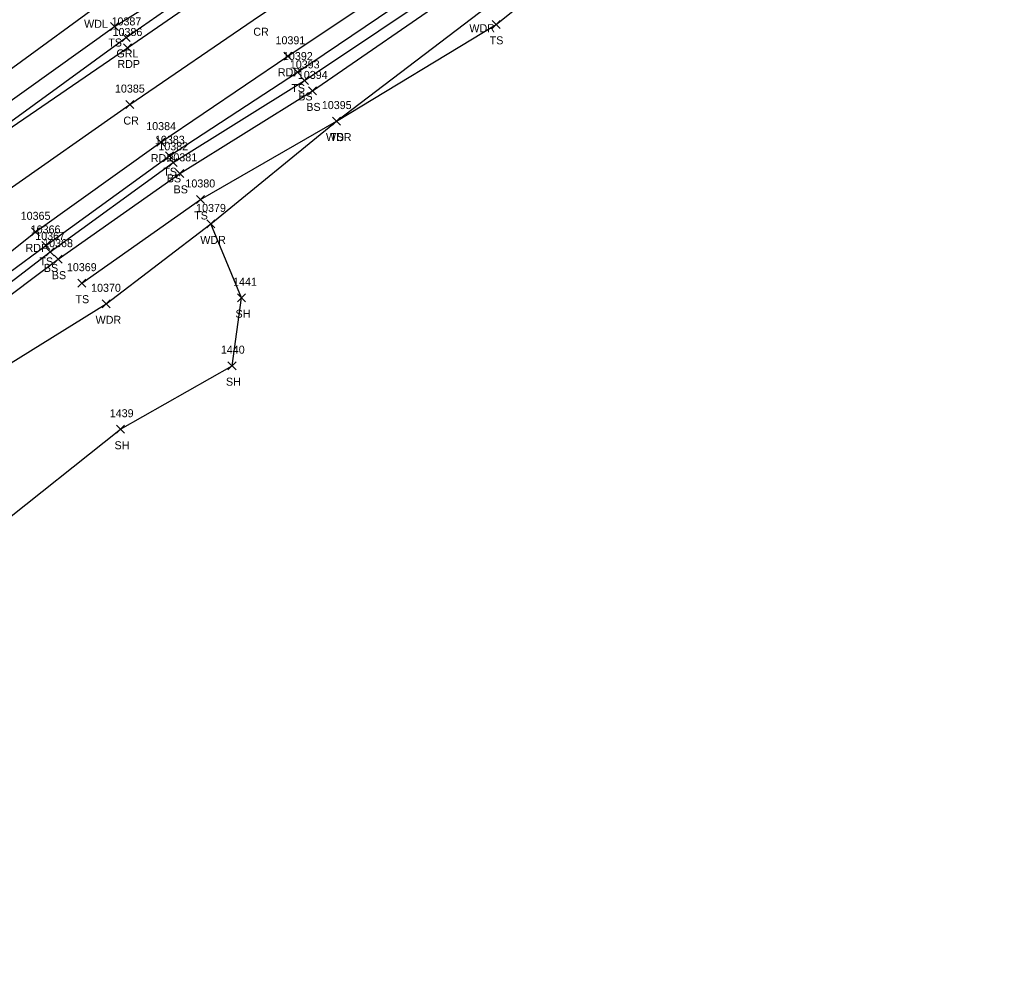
# Model space of a CAD drawing. Extents: x 1651685 to 1653558, y 889533 to 891085.
# Drawn here: x 1652940.5 to 1653187.7, y 890489.8 to 890725 of the extents above; entities that cross this region are included whole.
import ezdxf

# ---------------------------------------------------------------- set-up
doc = ezdxf.new("R2010")
doc.units = 0
for name, color, linetype in [('L_A', 7, 'Continuous'), ('L_I', 7, 'Continuous'), ('L_TIC', 7, 'Continuous'), ('LAWA', 7, 'Continuous'), ('LELB', 7, 'Continuous'), ('LSOGP', 7, 'Continuous'), ('P_A', 7, 'Continuous'), ('P_I', 7, 'Continuous'), ('P_TIC', 7, 'Continuous'), ('PET', 7, 'Continuous'), ('PRC', 7, 'Continuous'), ('R_A', 7, 'Continuous'), ('R_I', 7, 'Continuous'), ('R_TIC', 7, 'Continuous'), ('RGR', 7, 'Continuous')]:
    doc.layers.add(name, color=color, linetype=linetype)

msp = doc.modelspace()

# ---------------------------------------------------------------- linework, layer by layer
at = {"layer": 'L_TIC'}
for points in [[(1652963.24, 890722.35), (1652965.24, 890724.35)], [(1652965.24, 890722.35), (1652963.24, 890724.35)], [(1653058.51, 890722.89), (1653060.51, 890724.89)], [(1653060.51, 890722.89), (1653058.51, 890724.89)], [(1653008.95, 890710.96), (1653010.95, 890712.96)], [(1653010.95, 890710.96), (1653008.95, 890712.96)], [(1653010.67, 890708.88), (1653012.67, 890710.88)], [(1653012.67, 890708.88), (1653010.67, 890710.88)], [(1653012.67, 890706.26), (1653014.67, 890708.26)], [(1653014.67, 890706.26), (1653012.67, 890708.26)], [(1653018.66, 890698.72), (1653020.66, 890700.72)], [(1653020.66, 890698.72), (1653018.66, 890700.72)], [(1653018.66, 890698.72), (1653020.66, 890700.72)], [(1653020.66, 890698.72), (1653018.66, 890700.72)], [(1652976.97, 890690.06), (1652978.97, 890692.06)], [(1652978.97, 890690.06), (1652976.97, 890692.06)], [(1652977.83, 890688.41), (1652979.83, 890690.41)], [(1652979.83, 890688.41), (1652977.83, 890690.41)], [(1652979.52, 890685.66), (1652981.52, 890687.66)], [(1652981.52, 890685.66), (1652979.52, 890687.66)], [(1652984.68, 890679.14), (1652986.68, 890681.14)], [(1652986.68, 890679.14), (1652984.68, 890681.14)], [(1652987.27, 890673.02), (1652989.27, 890675.02)], [(1652989.27, 890673.02), (1652987.27, 890675.02)], [(1652946.04, 890667.65), (1652948.04, 890669.65)], [(1652948.04, 890667.65), (1652946.04, 890669.65)], [(1652947.11, 890666.03), (1652949.11, 890668.03)], [(1652949.11, 890666.03), (1652947.11, 890668.03)], [(1652949.1, 890664.22), (1652951.1, 890666.22)], [(1652951.1, 890664.22), (1652949.1, 890666.22)], [(1652955.04, 890658.22), (1652957.04, 890660.22)], [(1652957.04, 890658.22), (1652955.04, 890660.22)], [(1652994.94, 890654.58), (1652996.94, 890656.58)], [(1652996.94, 890654.58), (1652994.94, 890656.58)], [(1652961.12, 890653.07), (1652963.12, 890655.07)], [(1652963.12, 890653.07), (1652961.12, 890655.07)], [(1652992.55, 890637.61), (1652994.55, 890639.61)], [(1652994.55, 890637.61), (1652992.55, 890639.61)], [(1652964.72, 890621.73), (1652966.72, 890623.73)], [(1652966.72, 890621.73), (1652964.72, 890623.73)]]:
    msp.add_lwpolyline(points, dxfattribs=at)
at = {"layer": 'LAWA'}
for points in [[(1652817.98, 890613.54), (1652840.14, 890627.46), (1652861.15, 890647.29), (1652878.51, 890666.18), (1652884.26, 890671.52), (1652922.69, 890701.4), (1652959.19, 890728.02), (1652986.15, 890746.08), (1653025.9, 890769.89), (1653049.43, 890788.17), (1653075.47, 890803.38), (1653097.52, 890818.66), (1653132.33, 890844.48)], [(1652833.35, 890477.68), (1652833.39, 890492.3), (1652850.18, 890532.6), (1652867.73, 890564.2), (1652876.6, 890576.01), (1652892.95, 890598.85), (1652902.11, 890607.6), (1652908.8, 890618.44), (1652924.22, 890630.58), (1652962.12, 890654.07), (1652988.27, 890674.02), (1653019.66, 890699.72), (1653055.48, 890726.92), (1653095, 890752.3), (1653138.9, 890781.66), (1653162.63, 890798.14), (1653173.84, 890802.86)]]:
    msp.add_lwpolyline(points, dxfattribs=at)
at = {"layer": 'LELB'}
for points in [[(1652773.03, 890464.56), (1652787.9, 890509.35), (1652802.92, 890548.75), (1652814.17, 890571.87), (1652832.16, 890602.17), (1652848.73, 890624.66), (1652866.01, 890644.23), (1652889.12, 890668.57), (1652926.33, 890696.32), (1652964.24, 890723.35), (1652991.22, 890740.2), (1653028.13, 890766.86), (1653057.75, 890784.91), (1653079.01, 890799.53), (1653102.53, 890813.78), (1653139.28, 890840.79)], [(1652801.17, 890441.9), (1652819.95, 890497.78), (1652834.5, 890541.46), (1652846.59, 890562.12), (1652860.39, 890582.03), (1652876.07, 890602.68), (1652893.78, 890623.65), (1652912.56, 890642.08), (1652928.52, 890655.01), (1652947.04, 890668.65), (1652977.97, 890691.06), (1653009.95, 890711.96), (1653047.06, 890737.13), (1653086.67, 890762.46), (1653129.22, 890790.4), (1653161.56, 890810.77), (1653178.09, 890819.36), (1653180.64, 890814.31), (1653173.84, 890802.86)], [(1652803.19, 890441), (1652820.95, 890497.33), (1652835.58, 890541.15), (1652847.79, 890560.97), (1652861.63, 890580.86), (1652877.83, 890601.57), (1652890.21, 890617.22), (1652895.56, 890622.27), (1652897.12, 890622.95), (1652897.22, 890624.03), (1652915.57, 890639.3), (1652930.05, 890653.23), (1652948.11, 890667.03), (1652978.83, 890689.41), (1653011.67, 890709.88), (1653048.76, 890734.73), (1653087.02, 890761.14), (1653131.31, 890788.11), (1653159.98, 890805.73), (1653164.16, 890807.03), (1653164.17, 890807.66), (1653169.82, 890813.7), (1653178.09, 890819.36)], [(1652803.19, 890441), (1652822.35, 890480.19), (1652822.96, 890495.87), (1652838.19, 890539.83), (1652849.62, 890560.27), (1652863.19, 890579.04), (1652878.87, 890600.11), (1652891.82, 890615.8), (1652896.5, 890621.01), (1652897.47, 890622.7), (1652898.8, 890623.23), (1652915.57, 890639.3), (1652950.1, 890665.22), (1652980.52, 890686.66), (1653013.67, 890707.26), (1653050.87, 890733.01), (1653089.27, 890757.95), (1653133.42, 890785.98), (1653160.95, 890802.08), (1653164.63, 890804.85), (1653167.22, 890806.35), (1653170.81, 890811.17), (1653178.09, 890819.36)], [(1652956.04, 890659.22), (1652985.68, 890680.14), (1653019.66, 890699.72), (1653059.51, 890723.89)]]:
    msp.add_lwpolyline(points, dxfattribs=at)
at = {"layer": 'LSOGP'}
msp.add_lwpolyline([(1652860.84, 890470.43), (1652866.91, 890496.63), (1652876.03, 890531.03), (1652888.38, 890556.27), (1652912.99, 890585.04), (1652934.21, 890597.75), (1652965.72, 890622.73), (1652993.55, 890638.61), (1652995.94, 890655.58), (1652988.27, 890674.02), (1653019.66, 890699.72), (1653059.51, 890723.89), (1653095, 890752.3), (1653138.9, 890781.66), (1653162.63, 890798.14), (1653173.85, 890802.86), (1653182.19, 890805.28), (1653198.8, 890815.08)], dxfattribs=at)
at = {"layer": 'P_TIC'}
for points in [[(1652966.44, 890716.98), (1652968.44, 890718.98)], [(1652968.44, 890716.98), (1652966.44, 890718.98)], [(1653006.52, 890714.91), (1653008.52, 890716.91)], [(1653008.52, 890714.91), (1653006.52, 890716.91)], [(1652966.99, 890702.84), (1652968.99, 890704.84)], [(1652968.99, 890702.84), (1652966.99, 890704.84)], [(1652974.79, 890693.46), (1652976.79, 890695.46)], [(1652976.79, 890693.46), (1652974.79, 890695.46)], [(1652943.49, 890671.05), (1652945.49, 890673.05)], [(1652945.49, 890671.05), (1652943.49, 890673.05)]]:
    msp.add_lwpolyline(points, dxfattribs=at)
at = {"layer": 'PET'}
for points in [[(1652776.68, 890458.63), (1652791.9, 890507.53), (1652801.72, 890533.82), (1652810.09, 890553.36), (1652823.07, 890577.38), (1652836.65, 890598.71), (1652853.5, 890620.62), (1652874.5, 890644.55), (1652894.69, 890663.43), (1652909.83, 890677.02), (1652929.28, 890691.96), (1652967.44, 890717.98), (1652993.7, 890736.14), (1653032.31, 890761.89), (1653070.4, 890786.93), (1653112.15, 890813.99), (1653148.48, 890837.47), (1653192.87, 890865.71), (1653235.94, 890893.09), (1653280.18, 890921.16), (1653320.29, 890946.68)], [(1652797.7, 890444.76), (1652815.98, 890499.36), (1652826.44, 890526.94), (1652833.17, 890541.97), (1652844.38, 890563.93), (1652857.27, 890583.87), (1652872.84, 890604.95), (1652891.59, 890626.08), (1652910.84, 890643.86), (1652926.01, 890657.3), (1652944.49, 890672.05), (1652975.79, 890694.46), (1653007.52, 890715.91), (1653044.82, 890740.95), (1653083.79, 890766.34), (1653126.92, 890794.39), (1653162.42, 890817.19), (1653177.23, 890826.53), (1653212.82, 890849.27), (1653251.6, 890873.99), (1653294.22, 890900.69), (1653334.65, 890925.85)]]:
    msp.add_lwpolyline(points, dxfattribs=at)
at = {"layer": 'PRC'}
msp.add_lwpolyline([(1652786.21, 890448.94), (1652804.54, 890503.78), (1652815.08, 890532.72), (1652822.08, 890547.99), (1652834.04, 890571.05), (1652846.73, 890591.11), (1652862.72, 890612.73), (1652882.99, 890635.62), (1652902.76, 890654.37), (1652917.73, 890667.19), (1652936.47, 890681.71), (1652967.99, 890703.84), (1653000.43, 890726.04), (1653038.85, 890751.54), (1653077.14, 890776.73), (1653119.4, 890804.03), (1653156.21, 890827.39), (1653198.86, 890855.33), (1653243.54, 890883.44), (1653287.35, 890911.24), (1653327.74, 890936.2)], dxfattribs=at)
at = {"layer": 'R_TIC'}
for points in [[(1652966.13, 890719.62), (1652968.13, 890721.62)], [(1652968.13, 890719.62), (1652966.13, 890721.62)]]:
    msp.add_lwpolyline(points, dxfattribs=at)
at = {"layer": 'RGR'}
msp.add_lwpolyline([(1652753.62, 890407.5), (1652763.75, 890431.04), (1652774.48, 890459.79), (1652790.93, 890508.17), (1652800.51, 890534.29), (1652809.1, 890554.07), (1652821.88, 890578.18), (1652835.53, 890599.08), (1652852.44, 890621.25), (1652873.86, 890645.38), (1652894.3, 890664.88), (1652909.53, 890677.55), (1652928.71, 890692.69), (1652967.13, 890720.62), (1652991.99, 890738.03), (1653030.5, 890764.27), (1653069.01, 890789.08), (1653110.73, 890816.31), (1653147.12, 890839.54), (1653191.34, 890868.1), (1653234.07, 890895.44), (1653279.07, 890923.79), (1653318.83, 890948.74)], dxfattribs=at)

# ---------------------------------------------------------------- texts
at = {"layer": 'L_A'}
for s, p in [('WDL', (1652956.61, 890723.02)), ('WDR', (1653052.84, 890721.92)), ('TS', (1652962.65, 890718.35)), ('TS', (1653057.92, 890718.89)), ('TS', (1653008.36, 890706.96)), ('BS', (1653010.11, 890704.88)), ('BS', (1653012.11, 890702.26)), ('WDR', (1653017.02, 890694.72)), ('TS', (1653018.07, 890694.72)), ('TS', (1652976.38, 890686.06)), ('BS', (1652977.27, 890684.41)), ('BS', (1652978.96, 890681.66)), ('TS', (1652984.09, 890675.14)), ('WDR', (1652985.63, 890669.02)), ('TS', (1652945.45, 890663.65)), ('BS', (1652946.56, 890662.03)), ('BS', (1652948.54, 890660.22)), ('TS', (1652954.45, 890654.22)), ('WDR', (1652959.48, 890649.07)), ('SH', (1652994.43, 890650.58)), ('SH', (1652992.04, 890633.61)), ('SH', (1652964.21, 890617.73))]:
    msp.add_text(s, height=2, dxfattribs=at).set_placement(p)
at = {"layer": 'L_I'}
for s, p in [('10392', (1653006.28, 890714.96)), ('10393', (1653008, 890712.88)), ('10394', (1653010, 890710.26)), ('10395', (1653015.99, 890702.72)), ('10395', (1653015.99, 890702.72)), ('10383', (1652974.3, 890694.06)), ('10382', (1652975.16, 890692.41)), ('10381', (1652977.42, 890689.66)), ('10380', (1652981.92, 890683.14)), ('10379', (1652984.59, 890677.02)), ('10366', (1652943.27, 890671.65)), ('10367', (1652944.4, 890670.03)), ('10368', (1652946.38, 890668.22)), ('10369', (1652952.31, 890662.22)), ('10370', (1652958.36, 890657.07)), ('1441', (1652993.81, 890658.58)), ('1440', (1652990.77, 890641.61)), ('1439', (1652963.02, 890625.73))]:
    msp.add_text(s, height=2, dxfattribs=at).set_placement(p)
at = {"layer": 'P_A'}
for s, p in [('CR', (1652998.87, 890721.04)), ('RDP', (1652964.93, 890712.98)), ('RDP', (1653005.01, 890710.91)), ('CR', (1652966.42, 890698.84)), ('RDP', (1652973.28, 890689.46)), ('RDP', (1652941.98, 890667.05))]:
    msp.add_text(s, height=2, dxfattribs=at).set_placement(p)
at = {"layer": 'P_I'}
for s, p in [('10386', (1652963.72, 890720.98)), ('10391', (1653004.42, 890718.91)), ('10385', (1652964.32, 890706.84)), ('10384', (1652972.13, 890697.46)), ('10365', (1652940.77, 890675.05))]:
    msp.add_text(s, height=2, dxfattribs=at).set_placement(p)
at = {"layer": 'R_A'}
msp.add_text('GRL', height=2, dxfattribs=at).set_placement((1652964.67, 890715.62))
at = {"layer": 'R_I'}
msp.add_text('10387', height=2, dxfattribs=at).set_placement((1652963.46, 890723.62))

doc.saveas('drawing.dxf')
